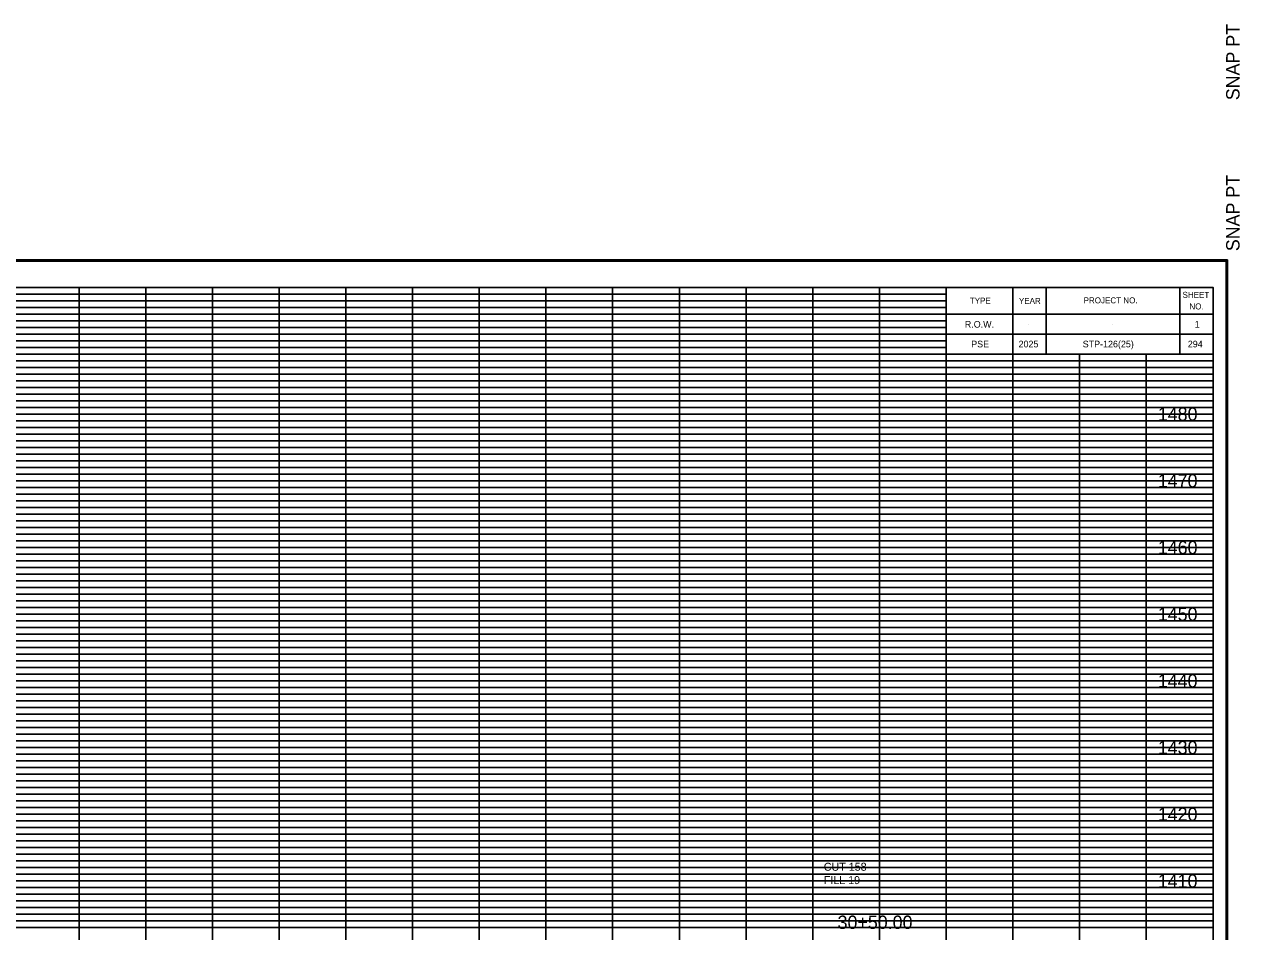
# Model space of a CAD drawing. Extents: x 980 to 2064, y 978 to 2267.
# Drawn here: x 1141.8 to 1324, y 1113.4 to 1249.4 of the extents above; entities that cross this region are included whole.
import ezdxf

# ---------------------------------------------------------------- set-up
doc = ezdxf.new("R2010")
doc.units = 0
for name, color, linetype in [('Default', 7, 'Continuous'), ('DESIGN - SCRATCH - User 1', 7, 'Continuous'), ('DESIGN - SHEET - Corner Text', 7, 'Continuous'), ('DESIGN - SHEET - Light Grid', 7, 'Continuous'), ('DESIGN - SHEET - Linework', 7, 'Continuous'), ('DESIGN - SHEET - Plot Shape', 7, 'Continuous'), ('DESIGN - TYPICAL - Text', 7, 'Continuous')]:
    doc.layers.add(name, color=color, linetype=linetype)

# ---------------------------------------------------------------- blocks, each defined once
blk = doc.blocks.new('XSTSHT')
at = {"layer": 'DESIGN - SCRATCH - User 1'}
for p, q in [((28.5, 20.45), (28.5, 20.45)), ((29.24, 20.45), (29.24, 20.45)), ((30.49, 20.45), (30.49, 20.45)), ((31.74, 20.45), (31.74, 20.45)), ((28.5, 20.15), (28.5, 20.15)), ((29.24, 20.15), (29.24, 20.15)), ((30.49, 20.15), (30.49, 20.15)), ((31.74, 20.15), (31.74, 20.15))]:
    blk.add_line(p, q, dxfattribs=at)
at = {"layer": 'DESIGN - SHEET - Light Grid'}
for p, q in [((8, 20.9), (16, 20.9)), ((8, 20.8), (16, 20.8)), ((16, 20.9), (24, 20.9)), ((16, 20.8), (24, 20.8)), ((24, 20.9), (28, 20.9)), ((24, 20.8), (28, 20.8)), ((8, 20.7), (16, 20.7)), ((8, 20.6), (16, 20.6)), ((16, 20.7), (24, 20.7)), ((16, 20.6), (24, 20.6)), ((24, 20.7), (28, 20.7)), ((24, 20.6), (28, 20.6)), ((8, 20.5), (16, 20.5)), ((16, 20.5), (24, 20.5)), ((24, 20.5), (28, 20.5)), ((8, 20.4), (16, 20.4)), ((8, 20.3), (16, 20.3)), ((16, 20.4), (24, 20.4)), ((16, 20.3), (24, 20.3)), ((24, 20.4), (28, 20.4)), ((24, 20.3), (28, 20.3)), ((8, 20.2), (16, 20.2)), ((8, 20.1), (16, 20.1)), ((16, 20.2), (24, 20.2)), ((16, 20.1), (24, 20.1)), ((24, 20.2), (28, 20.2)), ((24, 20.1), (28, 20.1)), ((8, 19.9), (16, 19.9)), ((16, 19.9), (24, 19.9)), ((24, 19.9), (32, 19.9)), ((8, 19.8), (16, 19.8)), ((8, 19.7), (16, 19.7)), ((16, 19.8), (24, 19.8)), ((16, 19.7), (24, 19.7)), ((24, 19.8), (32, 19.8)), ((24, 19.7), (32, 19.7)), ((8, 19.6), (16, 19.6)), ((8, 19.5), (16, 19.5)), ((16, 19.6), (24, 19.6)), ((16, 19.5), (24, 19.5)), ((24, 19.6), (32, 19.6)), ((24, 19.5), (32, 19.5)), ((8, 19.4), (16, 19.4)), ((16, 19.4), (24, 19.4)), ((24, 19.4), (32, 19.4)), ((8, 19.3), (16, 19.3)), ((8, 19.2), (16, 19.2)), ((16, 19.3), (24, 19.3)), ((16, 19.2), (24, 19.2)), ((24, 19.3), (32, 19.3)), ((24, 19.2), (32, 19.2)), ((8, 19.1), (16, 19.1)), ((16, 19.1), (24, 19.1)), ((24, 19.1), (32, 19.1)), ((8, 18.9), (16, 18.9)), ((8, 18.8), (16, 18.8)), ((16, 18.9), (24, 18.9)), ((16, 18.8), (24, 18.8)), ((24, 18.9), (32, 18.9)), ((24, 18.8), (32, 18.8)), ((8, 18.7), (16, 18.7)), ((8, 18.6), (16, 18.6)), ((16, 18.7), (24, 18.7)), ((16, 18.6), (24, 18.6)), ((24, 18.7), (32, 18.7)), ((24, 18.6), (32, 18.6)), ((8, 18.5), (16, 18.5)), ((16, 18.5), (24, 18.5)), ((24, 18.5), (32, 18.5)), ((8, 18.4), (16, 18.4)), ((8, 18.3), (16, 18.3)), ((16, 18.4), (24, 18.4)), ((16, 18.3), (24, 18.3)), ((24, 18.4), (32, 18.4)), ((24, 18.3), (32, 18.3)), ((8, 18.2), (16, 18.2)), ((8, 18.1), (16, 18.1)), ((16, 18.2), (24, 18.2)), ((16, 18.1), (24, 18.1)), ((24, 18.2), (32, 18.2)), ((24, 18.1), (32, 18.1)), ((8, 17.9), (16, 17.9)), ((16, 17.9), (24, 17.9)), ((24, 17.9), (32, 17.9)), ((8, 17.8), (16, 17.8)), ((8, 17.7), (16, 17.7)), ((16, 17.8), (24, 17.8)), ((16, 17.7), (24, 17.7)), ((24, 17.8), (32, 17.8)), ((24, 17.7), (32, 17.7)), ((8, 17.6), (16, 17.6)), ((8, 17.5), (16, 17.5)), ((16, 17.6), (24, 17.6)), ((16, 17.5), (24, 17.5)), ((24, 17.6), (32, 17.6)), ((24, 17.5), (32, 17.5)), ((8, 17.4), (16, 17.4)), ((16, 17.4), (24, 17.4)), ((24, 17.4), (32, 17.4)), ((8, 17.3), (16, 17.3)), ((8, 17.2), (16, 17.2)), ((16, 17.3), (24, 17.3)), ((16, 17.2), (24, 17.2)), ((24, 17.3), (32, 17.3)), ((24, 17.2), (32, 17.2)), ((8, 17.1), (16, 17.1)), ((16, 17.1), (24, 17.1)), ((24, 17.1), (32, 17.1)), ((8, 16.9), (16, 16.9)), ((8, 16.8), (16, 16.8)), ((16, 16.9), (24, 16.9)), ((16, 16.8), (24, 16.8)), ((24, 16.9), (32, 16.9)), ((24, 16.8), (32, 16.8)), ((8, 16.7), (16, 16.7)), ((8, 16.6), (16, 16.6)), ((16, 16.7), (24, 16.7)), ((16, 16.6), (24, 16.6)), ((24, 16.7), (32, 16.7)), ((24, 16.6), (32, 16.6)), ((8, 16.5), (16, 16.5)), ((8, 16.4), (16, 16.4)), ((16, 16.5), (24, 16.5)), ((16, 16.4), (24, 16.4)), ((24, 16.5), (32, 16.5)), ((24, 16.4), (32, 16.4)), ((8, 16.3), (16, 16.3)), ((16, 16.3), (24, 16.3)), ((24, 16.3), (32, 16.3)), ((8, 16.2), (16, 16.2)), ((8, 16.1), (16, 16.1)), ((16, 16.2), (24, 16.2)), ((16, 16.1), (24, 16.1)), ((24, 16.2), (32, 16.2)), ((24, 16.1), (32, 16.1)), ((8, 15.9), (16, 15.9)), ((16, 15.9), (24, 15.9)), ((24, 15.9), (32, 15.9)), ((8, 15.8), (16, 15.8)), ((8, 15.7), (16, 15.7)), ((16, 15.8), (24, 15.8)), ((16, 15.7), (24, 15.7)), ((24, 15.8), (32, 15.8)), ((24, 15.7), (32, 15.7)), ((8, 15.6), (16, 15.6)), ((8, 15.5), (16, 15.5)), ((16, 15.6), (24, 15.6)), ((16, 15.5), (24, 15.5)), ((24, 15.6), (32, 15.6)), ((24, 15.5), (32, 15.5)), ((8, 15.4), (16, 15.4)), ((16, 15.4), (24, 15.4)), ((24, 15.4), (32, 15.4)), ((8, 15.3), (16, 15.3)), ((8, 15.2), (16, 15.2)), ((16, 15.3), (24, 15.3)), ((16, 15.2), (24, 15.2)), ((24, 15.3), (32, 15.3)), ((24, 15.2), (32, 15.2)), ((8, 15.1), (16, 15.1)), ((16, 15.1), (24, 15.1)), ((24, 15.1), (32, 15.1)), ((8, 14.9), (16, 14.9)), ((8, 14.8), (16, 14.8)), ((16, 14.9), (24, 14.9)), ((16, 14.8), (24, 14.8)), ((24, 14.9), (32, 14.9)), ((24, 14.8), (32, 14.8)), ((8, 14.7), (16, 14.7)), ((8, 14.6), (16, 14.6)), ((16, 14.7), (24, 14.7)), ((16, 14.6), (24, 14.6)), ((24, 14.7), (32, 14.7)), ((24, 14.6), (32, 14.6)), ((8, 14.5), (16, 14.5)), ((8, 14.4), (16, 14.4)), ((16, 14.5), (24, 14.5)), ((16, 14.4), (24, 14.4)), ((24, 14.5), (32, 14.5)), ((24, 14.4), (32, 14.4)), ((8, 14.3), (16, 14.3)), ((16, 14.3), (24, 14.3)), ((24, 14.3), (32, 14.3)), ((8, 14.2), (16, 14.2)), ((8, 14.1), (16, 14.1)), ((16, 14.2), (24, 14.2)), ((16, 14.1), (24, 14.1)), ((24, 14.2), (32, 14.2)), ((24, 14.1), (32, 14.1)), ((8, 13.9), (16, 13.9)), ((16, 13.9), (24, 13.9)), ((24, 13.9), (32, 13.9)), ((8, 13.8), (16, 13.8)), ((8, 13.7), (16, 13.7)), ((16, 13.8), (24, 13.8)), ((16, 13.7), (24, 13.7)), ((24, 13.8), (32, 13.8)), ((24, 13.7), (32, 13.7)), ((8, 13.6), (16, 13.6)), ((8, 13.5), (16, 13.5)), ((16, 13.6), (24, 13.6)), ((16, 13.5), (24, 13.5)), ((24, 13.6), (32, 13.6)), ((24, 13.5), (32, 13.5)), ((8, 13.4), (16, 13.4)), ((16, 13.4), (24, 13.4)), ((24, 13.4), (32, 13.4)), ((8, 13.3), (16, 13.3)), ((8, 13.2), (16, 13.2)), ((16, 13.3), (24, 13.3)), ((16, 13.2), (24, 13.2)), ((24, 13.3), (32, 13.3)), ((24, 13.2), (32, 13.2)), ((8, 13.1), (16, 13.1)), ((16, 13.1), (24, 13.1)), ((24, 13.1), (32, 13.1)), ((8, 12.9), (16, 12.9)), ((8, 12.8), (16, 12.8)), ((16, 12.9), (24, 12.9)), ((16, 12.8), (24, 12.8)), ((24, 12.9), (32, 12.9)), ((24, 12.8), (32, 12.8)), ((8, 12.7), (16, 12.7)), ((8, 12.6), (16, 12.6)), ((16, 12.7), (24, 12.7)), ((16, 12.6), (24, 12.6)), ((24, 12.7), (32, 12.7)), ((24, 12.6), (32, 12.6)), ((8, 12.5), (16, 12.5)), ((8, 12.4), (16, 12.4)), ((16, 12.5), (24, 12.5)), ((16, 12.4), (24, 12.4)), ((24, 12.5), (32, 12.5)), ((24, 12.4), (32, 12.4)), ((8, 12.3), (16, 12.3)), ((16, 12.3), (24, 12.3)), ((24, 12.3), (32, 12.3)), ((8, 12.2), (16, 12.2)), ((8, 12.1), (16, 12.1)), ((16, 12.2), (24, 12.2)), ((16, 12.1), (24, 12.1)), ((24, 12.2), (32, 12.2)), ((24, 12.1), (32, 12.1)), ((8, 11.9), (16, 11.9)), ((16, 11.9), (24, 11.9)), ((24, 11.9), (32, 11.9)), ((8, 11.8), (16, 11.8)), ((8, 11.7), (16, 11.7)), ((16, 11.8), (24, 11.8)), ((16, 11.7), (24, 11.7)), ((24, 11.8), (32, 11.8)), ((24, 11.7), (32, 11.7)), ((8, 11.6), (16, 11.6)), ((8, 11.5), (16, 11.5)), ((16, 11.6), (24, 11.6)), ((16, 11.5), (24, 11.5)), ((24, 11.6), (32, 11.6)), ((24, 11.5), (32, 11.5)), ((8, 11.4), (16, 11.4)), ((16, 11.4), (24, 11.4)), ((24, 11.4), (32, 11.4))]:
    blk.add_line(p, q, dxfattribs=at)
at = {"layer": 'DESIGN - SHEET - Linework'}
for p, q in [((-1.823, 21.414), (32.217, 21.414)), ((32.217, 21.414), (32.217, -0.414)), ((15, 0), (15, 21)), ((16, 0), (16, 21)), ((17, 0), (17, 21)), ((18, 0), (18, 21)), ((19, 0), (19, 21)), ((20, 0), (20, 21)), ((21, 0), (21, 21)), ((22, 0), (22, 21)), ((23, 0), (23, 21)), ((24, 0), (24, 21)), ((25, 0), (25, 21)), ((26, 0), (26, 21)), ((27, 0), (27, 21)), ((0, 20), (28, 20)), ((28, 0), (28, 20)), ((29, 0), (29, 20)), ((30, 0), (30, 20)), ((31, 0), (31, 20)), ((0, 19), (32, 19)), ((0, 18), (32, 18)), ((0, 17), (32, 17)), ((0, 16), (32, 16)), ((0, 15), (32, 15)), ((0, 14), (32, 14)), ((0, 13), (32, 13)), ((0, 12), (32, 12))]:
    blk.add_line(p, q, dxfattribs=at)
for points in [[(0, 21), (0, 0), (32, 0), (32, 21), (0, 21)], [(28, 21), (28, 20), (32, 20), (32, 21), (31.5, 21), (31.5, 20), (29.5, 20), (29.5, 21), (29, 21), (29, 20), (32, 20), (28, 20), (28, 20.3), (32, 20.3), (32, 20.6), (28, 20.6)]]:
    blk.add_lwpolyline(points, dxfattribs=at)
at = {"layer": 'DESIGN - SHEET - Plot Shape'}
for points in [[(-1.803, 21.394), (32.197, 21.394), (32.197, -0.394), (-1.803, -0.394)], [(-0.85, 21), (32, 21), (32, -0.25), (-0.85, -0.25)]]:
    blk.add_lwpolyline(points, close=True, dxfattribs=at)
at = {"layer": 'DESIGN - SHEET - Corner Text'}
blk.add_text('  SNAP PT', height=0.2, rotation=90, dxfattribs=at).set_placement((32.397, 21.394))
for s, p in [('TYPE', (28.354, 20.756)), ('YEAR', (29.09, 20.752)), ('PROJECT NO.', (30.06, 20.76)), ('SHEET', (31.543, 20.843)), ('NO.', (31.646, 20.669))]:
    blk.add_text(s, height=0.09, dxfattribs=at).set_placement(p)

msp = doc.modelspace()

# ---------------------------------------------------------------- block references
at = {"layer": 'Default', "xscale": 10, "yscale": 10}
msp.add_blockref('XSTSHT', (1000, 1000), dxfattribs=at)

# ---------------------------------------------------------------- texts
at = {"layer": 'Default'}
for s, p in [('     1480     ', (1308.01, 1190)), ('     1470     ', (1308.01, 1180)), ('     1460     ', (1308.01, 1170)), ('     1450     ', (1308.01, 1160)), ('     1440     ', (1308.01, 1150)), ('     1430     ', (1308.01, 1140)), ('     1420     ', (1308.01, 1130)), ('     1410     ', (1308.01, 1120)), ('     30+50.00     ', (1260, 1113.81))]:
    msp.add_text(s, height=2, dxfattribs=at).set_placement(p)
at = {"layer": 'DESIGN - SHEET - Corner Text'}
msp.add_text('SNAP PT  ', height=2, rotation=90, dxfattribs=at).set_placement((1323.97, 1238.06))
for s, p in [('R.O.W.', (1282.79, 1203.96)), ('1', (1317.26, 1203.96)), ('PSE', (1283.75, 1201)), ('2025', (1290.85, 1201)), ('STP-126(25)', (1300.47, 1201)), ('294', (1316.22, 1201))]:
    msp.add_text(s, height=1, dxfattribs=at).set_placement(p)
at = {"layer": 'DESIGN - TYPICAL - Text'}
for s, p in [('CUT 158', (1261.65, 1122.53)), ('FILL 19', (1261.65, 1120.53))]:
    msp.add_text(s, height=1.2, dxfattribs=at).set_placement(p)

doc.saveas('drawing.dxf')
